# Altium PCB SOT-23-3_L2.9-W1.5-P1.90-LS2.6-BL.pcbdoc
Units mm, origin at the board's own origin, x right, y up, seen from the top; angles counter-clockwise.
Board outline 15.67 x 16.08 mm, 2 copper layers (Top Layer, Bottom Layer), stack 0 mm thick; 1 components, 0 nets, 3 pads, 0 vias.
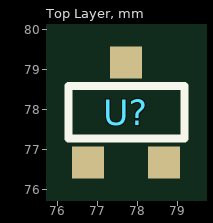
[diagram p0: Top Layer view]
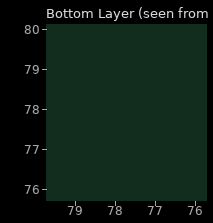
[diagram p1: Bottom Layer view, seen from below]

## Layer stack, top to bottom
Top Layer: signal copper (thickness not stored)
Bottom Layer: signal copper (thickness not stored)

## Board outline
85.52,69.85 69.85,69.85 69.85,85.93 85.52,85.93

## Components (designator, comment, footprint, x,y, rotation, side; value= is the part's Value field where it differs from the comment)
U? "" SOT-23-3_L2.9-W1.5-P1.90-LS2.6-BL 77.71,77.93 r0 top

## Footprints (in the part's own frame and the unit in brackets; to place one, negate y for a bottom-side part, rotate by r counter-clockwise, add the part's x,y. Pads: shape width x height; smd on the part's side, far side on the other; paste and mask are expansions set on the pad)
SOT-23-3_L2.9-W1.5-P1.90-LS2.6-BL [mm]
  rect 0.8x0.8 smd paste+0 mask+0.05: 1(-0.95,-1.25) 2(0.95,-1.25) 3(0,1.25)
  silkscreen extent -1.44,-0.66 1.46,0.66

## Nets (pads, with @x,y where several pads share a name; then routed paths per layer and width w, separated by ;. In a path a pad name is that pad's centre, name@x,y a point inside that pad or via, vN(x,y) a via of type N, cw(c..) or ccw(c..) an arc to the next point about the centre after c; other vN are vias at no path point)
pads on no net: U?.1 U?.2 U?.3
